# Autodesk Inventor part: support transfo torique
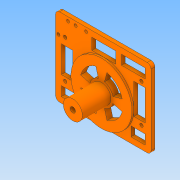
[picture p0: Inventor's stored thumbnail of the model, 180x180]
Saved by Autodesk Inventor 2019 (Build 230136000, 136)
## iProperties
Created: 2024-08
Part Number: support transfo torique
Material: Générique
Document SubType Name: Modeling
Designer: admin
Density: 1 g/cm^3
Appearance: Par défaut
Author: admin
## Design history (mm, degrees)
sketch "Esquisse1"
  geometry: L1 (-50, 40)-(50, 40); L2 (50, 40)-(50, -42); L3 (50, -42)-(-50, -42); L4 (-50, -42)-(-50, 40); L5 (-40, 20)-(0, 20); L6 (0, 20)-(0, -20); L7 (0, -20)-(-40, -20); L8 (-40, -20)-(-40, 20); L9 (0, 20)-(40, 20); L10 (40, 20)-(40, -20); L11 (40, -20)-(0, -20); L12 (0, -20)-(0, 20); C1 r 30 at (0, 0); 1 further point
  constraints: 24 end point, 6 parallel, 3 horizontal, 3 perpendicular, 1 centre point, 1 coincident
  dimensions: "d0" = 82 distance of L3.end L1.start; "d1" = 100 distance of L1.start L1.end; "d2" = 40 distance from line of point (0, 0) L1; "d3" = 50 distance from line of point (0, 0) L4 (= 0.5 x d1); "d4" = 20 distance between parallel lines of L1 L5; "d5" = 10 distance between parallel lines of L4 L8; "d6" = 40 distance of L5.start L5.end; "d7" = 40 distance between parallel lines of L5 L7; "d8" = 40 distance of L10.end L11.end; "d9" = 60 diameter of C1
extrude "Extrusion1" new body sketch "Esquisse1" distance "d10" = 4; taper "d11" = 0 deg
sketch "Esquisse2"
  geometry: L1 (-40, 20)-(0, 20) reference; L2 (0, 20)-(40, 20) reference; L3 (0, 20)-(0, -20) reference; L4 (40, 20)-(40, -20) reference; L5 (40, -20)-(0, -20) reference; L6 (0, -20)-(-40, -20) reference; L7 (-40, -20)-(-40, 20) reference; C1 r 30 at (0, 0) reference; 5 further points
  constraints: 4 coincident
hole "Perçage1" sketch "Esquisse2" at (-40, 20), (-40, -20), (40, -20), (40, 20) diameter "d12" = 3.5; stored, may be unused: countersink angle "d16" = 90 deg, drill point angle "d18" = 118 deg; dims "d13" = 7, "d14" = 4, "d15" = 2, "d17" = 10.4
sketch "Esquisse6"
  geometry: L1 (-50, -42)-(-50, 40) reference; L2 (-50, 40)-(-15, 40); L3 (-15, 40)-(-15, 15); L4 (-15, 15)-(-50, 15); L5 (-50, 15)-(-50, 40); 1 further point
  constraints: 8 end point, 2 parallel, 1 horizontal, 1 perpendicular
  dimensions: "d27" = 35 distance of L1.end L2.end; "d28" = 25 distance between parallel lines of L2 L4
sketch "Esquisse3"
  geometry: C1 r 32 at (0, -10); 1 further point
  constraints: 1 centre point
  dimensions: "d29" = 64 diameter of C1; "d30" = 10 distance of point (0, 0) C1.centre
extrude "Extrusion5" join sketch "Esquisse3" distance "d31" = 2; taper "d32" = 0 deg
sketch "Esquisse7"
  geometry: C1 r 32 at (0, 0) reference; C2 r 10 at (0, 0); 1 further point
  constraints: 1 centre point, 1 coincident
  dimensions: "d33" = 20 diameter of C2
extrude "Extrusion6" join sketch "Esquisse7" distance "d34" = 30; taper "d35" = 0 deg
sketch "Esquisse8"
  geometry: C1 r 2.75 at (0, 0); 1 further point
  constraints: 1 centre point
  dimensions: "d36" = 5.5 diameter of C1
extrude "Extrusion7" cut sketch "Esquisse8" extent not by distance; stored distance "d37" = 30; taper "d38" = 0 deg
sketch "Esquisse9"
  geometry: L1 (-50, 40)-(50, 40) reference; L2 (-44, 40)-(-21, 40); L3 (-21, 40)-(-21, 15); L4 (-21, 15)-(-44, 15); L5 (-44, 15)-(-44, 40); L6 (-50, 40)-(-50, -42) reference; L7 (-50, -42)-(-50, 40) reference; L8 (-50, 27.5)-(-14.788, 27.5); 5 further points
  constraints: 10 end point, 2 horizontal, 2 parallel, 2 point on line, 1 perpendicular
  dimensions: "d39" = 25 distance of L2.end L3.end; "d40" = 6 distance between parallel lines of L5 L6; "d41" = 23 distance between parallel lines of L5 L3; "d42" = 4 distance from line of L1 point (-18, 36); "d43" = 4 distance from line of L4 point (-47, 19); "d44" = 3 distance from line of L6 point (-47, 19); "d45" = 3 distance from line of L3 point (-18, 36); "d89" = 8 distance of point (-29, 36) point (-37, 36); "d90" = 7 distance from line of L5 point (-37, 36)
hole "Perçage2" sketch "Esquisse9" at (-47, 19), (-18, 36), (-37, 36), (-29, 36) diameter "d46" = 3.15; stored, may be unused: countersink angle "d50" = 90 deg, drill point angle "d52" = 118 deg; dims "d47" = 8, "d48" = 4, "d49" = 2, "d51" = 11.8
sketch "Esquisse10"
  geometry: L1 (-44, 12)-(-32, 12); L2 (-32, 12)-(-32, -16); L3 (-32, -16)-(-44, -16); L4 (-44, -16)-(-44, 12); L5 (-44, -26)-(-29, -26); L6 (-29, -26)-(-29, -36); L7 (-29, -36)-(-44, -36); L8 (-44, -36)-(-44, -26); L9 (29, -26)-(44, -26); L10 (44, -26)-(44, -36); L11 (44, -36)-(29, -36); L12 (29, -36)-(29, -26); L13 (-50, 40)-(-50, -42) reference; L14 (-50, -42)-(50, -42) reference; L15 (50, -42)-(50, 40) reference; L16 (44, -16)-(32, -16); L17 (32, -16)-(32, 16); L18 (32, 16)-(44, 16); L19 (44, 16)-(44, -16); L20 (-12, 34)-(13, 34); L21 (13, 34)-(13, 22); L22 (13, 22)-(-12, 22); L23 (-12, 22)-(-12, 34); L24 (19, 34)-(44, 34); L25 (44, 34)-(44, 24); L26 (44, 24)-(19, 24); L27 (19, 24)-(19, 34); L28 (50, 40)-(-50, 40) reference; C1 r 10 at (0, -10) reference; A1 r 32 centre (0, -10) between (0, -42) and (-11.136, -40) reference; 1 further point; 1 other entity
  constraints: 48 end point, 12 parallel, 6 horizontal, 6 perpendicular, 3 point on line, 1 other
  dimensions: "d53" = 6 distance between parallel lines of L13 L8; "d54" = 6 dimension on L7; "d55" = 10 distance between parallel lines of L3 L5; "d56" = 28 distance of L3.end L1.start; "d57" = 12 distance of L2.end L3.end; "d58" = 15 distance of L6.end L7.end; "d59" = 10 distance of L7.end L5.start; "d60" = 6 distance between parallel lines of L14 L11; "d61" = 6 distance between parallel lines of L15 L10; "d62" = 15 distance of L10.end L11.end; "d63" = 10 distance of L9.end L10.end (derived); "d64" = 12 distance of L17.end L18.end; "d65" = 6 distance between parallel lines of L15 L19; "d66" = 10 distance between parallel lines of L9 L16; "d67" = 32 distance of L18.end L16.start; "d68" = 6 distance between parallel lines of L15 L25; "d69" = 6 distance between parallel lines of L28 L24; "d70" = 6 distance between parallel lines of L27 L21; "d71" = 25 distance between parallel lines of L21 L23; "d72" = 25 distance of L24.start L24.end; "d73" = 10 distance of L24.end L25.end; "d74" = 12 distance of L20.end L21.end
extrude "Extrusion8" cut sketch "Esquisse10" distance "d75" = 30; taper "d76" = 0 deg
sketch "Esquisse11" dims "d77" = 25, "d78" = 45
  geometry: L1 (32, -6)-(32, 26) reference; L2 (-3.235, 12.074)-(-5.823, 21.733); L3 (3.235, 12.074)-(5.823, 21.733); L4 (-12.074, 3.235)-(-21.733, 5.823); L5 (-12.074, -3.235)-(-21.733, -5.823); L6 (-3.235, -12.074)-(-5.823, -21.733); L7 (3.235, -12.074)-(5.823, -21.733); L8 (12.074, -3.235)-(21.733, -5.823); L9 (12.074, 3.235)-(21.733, 5.823); L10 (0, -22.5)-(0, -32); L11 (-32, 0)-(-22.5, 0); L12 (0, 42.126)-(0, 22.5); L13 (0, 12.5)-(0, -12.5); L14 (-12.5, 0)-(12.5, 0); L15 (22.5, 0)-(32, 0); A1 r 32 centre (0, 0) between (0, -32) and (-32, 0) reference; 3 further points
  constraints: 28 end point, 4 perpendicular, 3 point on circle, 3 vertical, 2 coincident, 28 other
  dimensions: "d82" = 30 deg angle of L4 L5; "d84" = 30 deg angle of L7 L6; "d86" = 30 deg angle of L8 L9
extrude "Extrusion9" cut sketch "Esquisse11" distance "d87" = 30; taper "d88" = 0 deg
fillet "Congé1" dims "d91" = 4
node "Solide1"
node "Boucle projetée1"
node "Boucle projetée2"
other parameters: "d79" = 15 deg, "d80" = 15 deg, "d81" = 15 deg, "d83" = 15 deg (derived), "d85" = 15 deg
